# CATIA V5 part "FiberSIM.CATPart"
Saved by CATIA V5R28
Part number: FiberSIM
Bounding box of the stored display mesh (mm): x -54 to 96, y -104.114 to 14.853, z -24.35 to 72.398
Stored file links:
  C:\Users\jvl2147\Documents\2CES-COEXISTENCE\FiberSIM.CATPart
  C:\Users\jvl2147\Documents\ASME Y14.37\PartExamples\ASME-Y14.37_COMPOSITES-A.CATMaterial
  C:\Program Files\Dassault Systemes\B28SP3PRALL\win_b64\startup\composites\LaminateColors.txt
  C:\Program Files\Dassault Systemes\B28SP3PRALL\win_b64\startup\composites\DropOffPattern1BackSlash.txt
  C:\Program Files\Dassault Systemes\B28SP3PRALL\win_b64\startup\composites\DropOffPattern1Backslash.txt
  C:\Program Files\Dassault Systemes\B28SP3PRALL\win_b64\startup\composites\DropOffPattern1InverseV.txt
  C:\Program Files\Dassault Systemes\B28SP3PRALL\win_b64\startup\composites\DropOffPattern1InverseW.txt
  C:\Program Files\Dassault Systemes\B28SP3PRALL\win_b64\startup\composites\DropOffPattern1Slash.txt
  C:\Program Files\Dassault Systemes\B28SP3PRALL\win_b64\startup\composites\DropOffPattern1V.txt
  C:\Program Files\Dassault Systemes\B28SP3PRALL\win_b64\startup\composites\DropOffPattern1V_Symetry.txt
  C:\Program Files\Dassault Systemes\B28SP3PRALL\win_b64\startup\composites\DropOffPattern1V_Symetry_2Consecutive.txt
  C:\Program Files\Dassault Systemes\B28SP3PRALL\win_b64\startup\composites\DropOffPattern1W.txt
  C:\Program Files\Dassault Systemes\B28SP3PRALL\win_b64\startup\composites\DropOffPattern2Cross.txt
  C:\Program Files\Dassault Systemes\B28SP3PRALL\win_b64\startup\composites\DropOffPattern2Diamond.txt
  C:\Program Files\Dassault Systemes\B28SP3PRALL\win_b64\startup\composites\DropOffPattern2Socks.txt
  C:\Program Files\Dassault Systemes\B28SP3PRALL\win_b64\startup\composites\DropOffPattern45AfterOthers.txt
  C:\Program Files\Dassault Systemes\B28SP3PRALL\win_b64\startup\composites\DropOffPattern4TwinDiamonds45.txt
  C:\Program Files\Dassault Systemes\B28SP3PRALL\win_b64\startup\composites\DropOffPattern5Cross_Pseudo_Sym.txt
  C:\Program Files\Dassault Systemes\B28SP3PRALL\win_b64\startup\composites\DropOffPattern5Diamond_Pseudo_Sym.txt
  C:\Program Files\Dassault Systemes\B28SP3PRALL\win_b64\startup\composites\DropOffPattern5Socks_Pseudo_Sym.txt
  C:\Users\jvl2147\Desktop\LaserExportTest.ply
  C:\Users\jvl2147\Documents\2CES-COEXISTENCE\PlyTable.xlsx
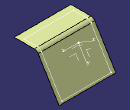
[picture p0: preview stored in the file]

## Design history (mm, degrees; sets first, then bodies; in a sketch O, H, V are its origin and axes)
Parameters
  `MBD Version - 787N4-1115 Rev` = "A"
AxisSystem1: origin (0, -29.9559, 49.1095), X (1, 0, 0), Y (0, 0.5207, -0.8537), Z (0, 0.8537, 0.5207)
Set1 "CONSTRUCTION DATA"
  Sketch1 on yz-plane, origin (0, 0, 0), H (0, 1, 0), V (0, 0, 1)
    line L1 (-104.1144, 72.3983) -> (-50.835, 72.3983)
    line L2 (-40.6865, 66.7012) -> (14.853, -24.35)
    arc A1 centre (-50.835, 60.5109) radius 11.8875 from (-50.835, 72.3983) to (-40.6865, 66.7012) cw
    radius A1 = 11.8875
    horizontal: L1 H
    coincidence: L2 O
    tangency: A1 L1, A1 L2
  Extrude1: Element1 Sketch1, Lim1 96, Lim2 54
  Plane1: type Offset, RefPlane yz-plane, Offset 87
  Plane2: type Offset, RefPlane yz-plane, Offset 44, reversed
  Plane3: type Offset, RefPlane zx-plane, Offset -87
  Plane4: type Offset, RefPlane xy-plane, Offset -20
  MultiSel1
  Point1: type OnCurve, Support Sketch1, Ratio 0.5
  Line1: type Normal, RefPoint Point1, RefSkin Extrude1, Start 0, End 20
  Plane5: type Offset, RefPlane ZX plane of AxisSystem1, Offset 20
  Set2 "PlyBoundaryCurves for - Boeing MBD"
    DatumCurve1 to DatumCurve32
Set3 "ENGINEERING DATA"
  Set4 "COMPOSITES DEFINITION DATA"
    AxisSystem2 "Rosette": origin (0, -29.9559, 49.1095), X (1, 0, 0), Y (0, 0.5207, -0.8537), Z (0, 0.8537, 0.5207)
    DatumSurface1 "Definition Surface": linked copy from another document
    CompStdContourFeature1 "EEOP": SupportSurface DatumSurface1, ClosedSetOfCurves ({intersect ToIntersect1 Extrude1, ToIntersect2 Plane2}; {intersect ToIntersect1 Extrude1, ToIntersect2 Plane4}; {intersect ToIntersect1 Extrude1, ToIntersect2 Plane1}; {intersect ToIntersect1 Extrude1, ToIntersect2 Plane3}), ExtrapolDist 0.2
Body1 (main body)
